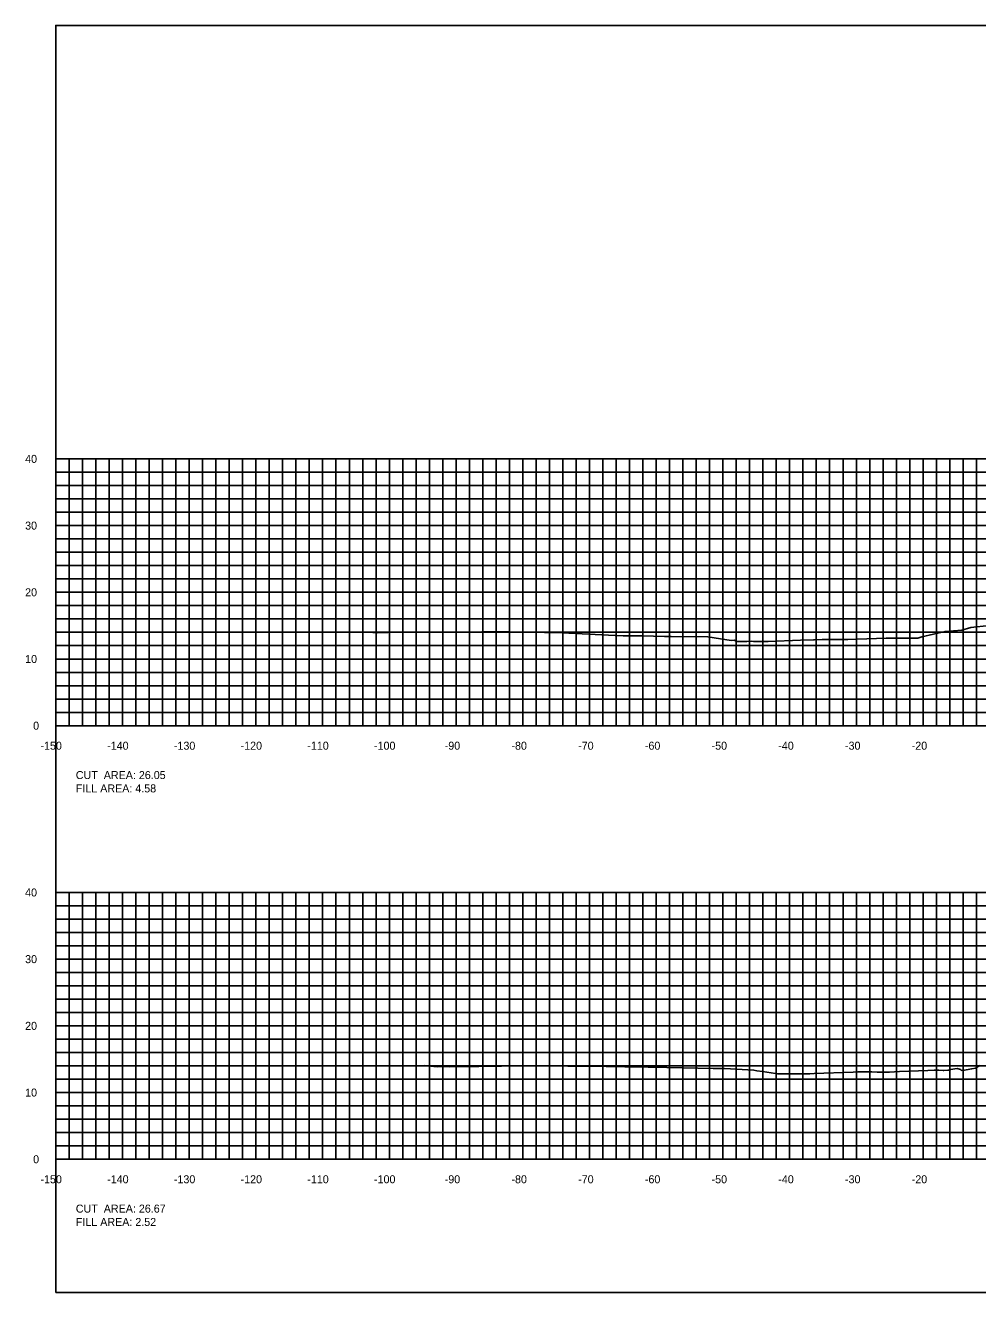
# Model space of a CAD drawing. Extents: x 1797652 to 1804159, y 242516 to 246906.
# Drawn here: x 1802149.9 to 1802292.7, y 242516 to 242706 of the extents above; entities that cross this region are included whole.
import ezdxf

# ---------------------------------------------------------------- set-up
doc = ezdxf.new("R2010")
doc.units = 0
for name, color, linetype in [('10', 7, 'Continuous'), ('31', 7, 'Continuous'), ('60', 7, 'Continuous'), ('Level 62', 7, 'Continuous'), ('M-ROADS', 7, 'Continuous')]:
    doc.layers.add(name, color=color, linetype=linetype)

msp = doc.modelspace()

# ---------------------------------------------------------------- linework, layer by layer
msp.add_lwpolyline([(1802154.49, 242516), (1802454.49, 242516), (1802454.49, 242706), (1802154.49, 242706)], close=True)
at = {"layer": '60'}
for p, q in [((1802154.43, 242641), (1802154.49, 242641)), ((1802154.49, 242601), (1802154.49, 242641)), ((1802154.43, 242631), (1802154.49, 242631)), ((1802154.43, 242621), (1802154.49, 242621)), ((1802154.43, 242611), (1802154.49, 242611)), ((1802154.43, 242601), (1802154.49, 242601)), ((1802154.49, 242601), (1802454.49, 242601)), ((1802154.49, 242600.94), (1802154.49, 242601)), ((1802164.49, 242600.94), (1802164.49, 242601)), ((1802174.49, 242600.94), (1802174.49, 242601)), ((1802184.49, 242600.94), (1802184.49, 242601)), ((1802194.49, 242600.94), (1802194.49, 242601)), ((1802204.49, 242600.94), (1802204.49, 242601)), ((1802214.49, 242600.94), (1802214.49, 242601)), ((1802224.49, 242600.94), (1802224.49, 242601)), ((1802234.49, 242600.94), (1802234.49, 242601)), ((1802244.49, 242600.94), (1802244.49, 242601)), ((1802254.49, 242600.94), (1802254.49, 242601)), ((1802264.49, 242600.94), (1802264.49, 242601)), ((1802274.49, 242600.94), (1802274.49, 242601)), ((1802284.49, 242600.94), (1802284.49, 242601)), ((1802154.43, 242576), (1802154.49, 242576)), ((1802154.49, 242536), (1802154.49, 242576)), ((1802154.43, 242566), (1802154.49, 242566)), ((1802154.43, 242556), (1802154.49, 242556)), ((1802154.43, 242546), (1802154.49, 242546)), ((1802154.43, 242536), (1802154.49, 242536)), ((1802154.49, 242536), (1802454.49, 242536)), ((1802154.49, 242535.94), (1802154.49, 242536)), ((1802164.49, 242535.94), (1802164.49, 242536)), ((1802174.49, 242535.94), (1802174.49, 242536)), ((1802184.49, 242535.94), (1802184.49, 242536)), ((1802194.49, 242535.94), (1802194.49, 242536)), ((1802204.49, 242535.94), (1802204.49, 242536)), ((1802214.49, 242535.94), (1802214.49, 242536)), ((1802224.49, 242535.94), (1802224.49, 242536)), ((1802234.49, 242535.94), (1802234.49, 242536)), ((1802244.49, 242535.94), (1802244.49, 242536)), ((1802254.49, 242535.94), (1802254.49, 242536)), ((1802264.49, 242535.94), (1802264.49, 242536)), ((1802274.49, 242535.94), (1802274.49, 242536)), ((1802284.49, 242535.94), (1802284.49, 242536))]:
    msp.add_line(p, q, dxfattribs=at)
at = {"layer": 'Level 62'}
for p, q in [((1802154.49, 242641), (1802454.49, 242641)), ((1802154.49, 242601), (1802154.49, 242641)), ((1802156.49, 242601), (1802156.49, 242641)), ((1802158.49, 242601), (1802158.49, 242641)), ((1802160.49, 242601), (1802160.49, 242641)), ((1802162.49, 242601), (1802162.49, 242641)), ((1802164.49, 242601), (1802164.49, 242641)), ((1802166.49, 242601), (1802166.49, 242641)), ((1802168.49, 242601), (1802168.49, 242641)), ((1802170.49, 242601), (1802170.49, 242641)), ((1802172.49, 242601), (1802172.49, 242641)), ((1802174.49, 242601), (1802174.49, 242641)), ((1802176.49, 242601), (1802176.49, 242641)), ((1802178.49, 242601), (1802178.49, 242641)), ((1802180.49, 242601), (1802180.49, 242641)), ((1802182.49, 242601), (1802182.49, 242641)), ((1802184.49, 242601), (1802184.49, 242641)), ((1802186.49, 242601), (1802186.49, 242641)), ((1802188.49, 242601), (1802188.49, 242641)), ((1802190.49, 242601), (1802190.49, 242641)), ((1802192.49, 242601), (1802192.49, 242641)), ((1802194.49, 242601), (1802194.49, 242641)), ((1802196.49, 242601), (1802196.49, 242641)), ((1802198.49, 242601), (1802198.49, 242641)), ((1802200.49, 242601), (1802200.49, 242641)), ((1802202.49, 242601), (1802202.49, 242641)), ((1802204.49, 242601), (1802204.49, 242641)), ((1802206.49, 242601), (1802206.49, 242641)), ((1802208.49, 242601), (1802208.49, 242641)), ((1802210.49, 242601), (1802210.49, 242641)), ((1802212.49, 242601), (1802212.49, 242641)), ((1802214.49, 242601), (1802214.49, 242641)), ((1802216.49, 242601), (1802216.49, 242641)), ((1802218.49, 242601), (1802218.49, 242641)), ((1802220.49, 242601), (1802220.49, 242641)), ((1802222.49, 242601), (1802222.49, 242641)), ((1802224.49, 242601), (1802224.49, 242641)), ((1802226.49, 242601), (1802226.49, 242641)), ((1802228.49, 242601), (1802228.49, 242641)), ((1802230.49, 242601), (1802230.49, 242641)), ((1802232.49, 242601), (1802232.49, 242641)), ((1802234.49, 242601), (1802234.49, 242641)), ((1802236.49, 242601), (1802236.49, 242641)), ((1802238.49, 242601), (1802238.49, 242641)), ((1802240.49, 242601), (1802240.49, 242641)), ((1802242.49, 242601), (1802242.49, 242641)), ((1802244.49, 242601), (1802244.49, 242641)), ((1802246.49, 242601), (1802246.49, 242641)), ((1802248.49, 242601), (1802248.49, 242641)), ((1802250.49, 242601), (1802250.49, 242641)), ((1802252.49, 242601), (1802252.49, 242641)), ((1802254.49, 242601), (1802254.49, 242641)), ((1802256.49, 242601), (1802256.49, 242641)), ((1802258.49, 242601), (1802258.49, 242641)), ((1802260.49, 242601), (1802260.49, 242641)), ((1802262.49, 242601), (1802262.49, 242641)), ((1802264.49, 242601), (1802264.49, 242641)), ((1802266.49, 242601), (1802266.49, 242641)), ((1802268.49, 242601), (1802268.49, 242641)), ((1802270.49, 242601), (1802270.49, 242641)), ((1802272.49, 242601), (1802272.49, 242641)), ((1802274.49, 242601), (1802274.49, 242641)), ((1802276.49, 242601), (1802276.49, 242641)), ((1802278.49, 242601), (1802278.49, 242641)), ((1802280.49, 242601), (1802280.49, 242641)), ((1802282.49, 242601), (1802282.49, 242641)), ((1802284.49, 242601), (1802284.49, 242641)), ((1802286.49, 242601), (1802286.49, 242641)), ((1802288.49, 242601), (1802288.49, 242641)), ((1802290.49, 242601), (1802290.49, 242641)), ((1802292.49, 242601), (1802292.49, 242641)), ((1802154.49, 242639), (1802454.49, 242639)), ((1802154.49, 242637), (1802454.49, 242637)), ((1802154.49, 242635), (1802454.49, 242635)), ((1802154.49, 242633), (1802454.49, 242633)), ((1802154.49, 242631), (1802454.49, 242631)), ((1802154.49, 242629), (1802454.49, 242629)), ((1802154.49, 242627), (1802454.49, 242627)), ((1802154.49, 242625), (1802454.49, 242625)), ((1802154.49, 242623), (1802454.49, 242623)), ((1802154.49, 242621), (1802454.49, 242621)), ((1802154.49, 242619), (1802454.49, 242619)), ((1802154.49, 242617), (1802454.49, 242617)), ((1802154.49, 242615), (1802454.49, 242615)), ((1802154.49, 242613), (1802454.49, 242613)), ((1802154.49, 242611), (1802454.49, 242611)), ((1802154.49, 242609), (1802454.49, 242609)), ((1802154.49, 242607), (1802454.49, 242607)), ((1802154.49, 242605), (1802454.49, 242605)), ((1802154.49, 242603), (1802454.49, 242603)), ((1802154.49, 242601), (1802454.49, 242601)), ((1802154.49, 242576), (1802454.49, 242576)), ((1802154.49, 242536), (1802154.49, 242576)), ((1802156.49, 242536), (1802156.49, 242576)), ((1802158.49, 242536), (1802158.49, 242576)), ((1802160.49, 242536), (1802160.49, 242576)), ((1802162.49, 242536), (1802162.49, 242576)), ((1802164.49, 242536), (1802164.49, 242576)), ((1802166.49, 242536), (1802166.49, 242576)), ((1802168.49, 242536), (1802168.49, 242576)), ((1802170.49, 242536), (1802170.49, 242576)), ((1802172.49, 242536), (1802172.49, 242576)), ((1802174.49, 242536), (1802174.49, 242576)), ((1802176.49, 242536), (1802176.49, 242576)), ((1802178.49, 242536), (1802178.49, 242576)), ((1802180.49, 242536), (1802180.49, 242576)), ((1802182.49, 242536), (1802182.49, 242576)), ((1802184.49, 242536), (1802184.49, 242576)), ((1802186.49, 242536), (1802186.49, 242576)), ((1802188.49, 242536), (1802188.49, 242576)), ((1802190.49, 242536), (1802190.49, 242576)), ((1802192.49, 242536), (1802192.49, 242576)), ((1802194.49, 242536), (1802194.49, 242576)), ((1802196.49, 242536), (1802196.49, 242576)), ((1802198.49, 242536), (1802198.49, 242576)), ((1802200.49, 242536), (1802200.49, 242576)), ((1802202.49, 242536), (1802202.49, 242576)), ((1802204.49, 242536), (1802204.49, 242576)), ((1802206.49, 242536), (1802206.49, 242576)), ((1802208.49, 242536), (1802208.49, 242576)), ((1802210.49, 242536), (1802210.49, 242576)), ((1802212.49, 242536), (1802212.49, 242576)), ((1802214.49, 242536), (1802214.49, 242576)), ((1802216.49, 242536), (1802216.49, 242576)), ((1802218.49, 242536), (1802218.49, 242576)), ((1802220.49, 242536), (1802220.49, 242576)), ((1802222.49, 242536), (1802222.49, 242576)), ((1802224.49, 242536), (1802224.49, 242576)), ((1802226.49, 242536), (1802226.49, 242576)), ((1802228.49, 242536), (1802228.49, 242576)), ((1802230.49, 242536), (1802230.49, 242576)), ((1802232.49, 242536), (1802232.49, 242576)), ((1802234.49, 242536), (1802234.49, 242576)), ((1802236.49, 242536), (1802236.49, 242576)), ((1802238.49, 242536), (1802238.49, 242576)), ((1802240.49, 242536), (1802240.49, 242576)), ((1802242.49, 242536), (1802242.49, 242576)), ((1802244.49, 242536), (1802244.49, 242576)), ((1802246.49, 242536), (1802246.49, 242576)), ((1802248.49, 242536), (1802248.49, 242576)), ((1802250.49, 242536), (1802250.49, 242576)), ((1802252.49, 242536), (1802252.49, 242576)), ((1802254.49, 242536), (1802254.49, 242576)), ((1802256.49, 242536), (1802256.49, 242576)), ((1802258.49, 242536), (1802258.49, 242576)), ((1802260.49, 242536), (1802260.49, 242576)), ((1802262.49, 242536), (1802262.49, 242576)), ((1802264.49, 242536), (1802264.49, 242576)), ((1802266.49, 242536), (1802266.49, 242576)), ((1802268.49, 242536), (1802268.49, 242576)), ((1802270.49, 242536), (1802270.49, 242576)), ((1802272.49, 242536), (1802272.49, 242576)), ((1802274.49, 242536), (1802274.49, 242576)), ((1802276.49, 242536), (1802276.49, 242576)), ((1802278.49, 242536), (1802278.49, 242576)), ((1802280.49, 242536), (1802280.49, 242576)), ((1802282.49, 242536), (1802282.49, 242576)), ((1802284.49, 242536), (1802284.49, 242576)), ((1802286.49, 242536), (1802286.49, 242576)), ((1802288.49, 242536), (1802288.49, 242576)), ((1802290.49, 242536), (1802290.49, 242576)), ((1802292.49, 242536), (1802292.49, 242576)), ((1802154.49, 242574), (1802454.49, 242574)), ((1802154.49, 242572), (1802454.49, 242572)), ((1802154.49, 242570), (1802454.49, 242570)), ((1802154.49, 242568), (1802454.49, 242568)), ((1802154.49, 242566), (1802454.49, 242566)), ((1802154.49, 242564), (1802454.49, 242564)), ((1802154.49, 242562), (1802454.49, 242562)), ((1802154.49, 242560), (1802454.49, 242560)), ((1802154.49, 242558), (1802454.49, 242558)), ((1802154.49, 242556), (1802454.49, 242556)), ((1802154.49, 242554), (1802454.49, 242554)), ((1802154.49, 242552), (1802454.49, 242552)), ((1802154.49, 242550), (1802454.49, 242550)), ((1802154.49, 242548), (1802454.49, 242548)), ((1802154.49, 242546), (1802454.49, 242546)), ((1802154.49, 242544), (1802454.49, 242544)), ((1802154.49, 242542), (1802454.49, 242542)), ((1802154.49, 242540), (1802454.49, 242540)), ((1802154.49, 242538), (1802454.49, 242538)), ((1802154.49, 242536), (1802454.49, 242536))]:
    msp.add_line(p, q, dxfattribs=at)
at = {"layer": 'M-ROADS'}
for points in [[(1802202.03, 242614.98), (1802202.64, 242614.93), (1802204.32, 242614.97), (1802207.14, 242615), (1802207.81, 242615), (1802212.75, 242615.04), (1802213.55, 242615.04), (1802215.54, 242615.04), (1802218.36, 242615.05), (1802221.28, 242615.05), (1802222.45, 242615.05), (1802230.38, 242614.94), (1802238.36, 242614.51), (1802239.54, 242614.49), (1802242.43, 242614.46), (1802245.73, 242614.37), (1802246.75, 242614.38), (1802252.21, 242614.32), (1802255.71, 242613.76), (1802256.23, 242613.8), (1802256.48, 242613.63), (1802257.59, 242613.64), (1802258.09, 242613.63), (1802258.83, 242613.65), (1802259.09, 242613.64), (1802259.65, 242613.61), (1802259.94, 242613.62), (1802261.26, 242613.64), (1802266.12, 242613.81), (1802268.09, 242613.87), (1802268.24, 242613.89), (1802269.38, 242613.92), (1802270.02, 242613.92), (1802270.13, 242613.92), (1802270.3, 242613.91), (1802271.08, 242613.91), (1802271.58, 242613.9), (1802272.65, 242613.92), (1802273.19, 242613.92), (1802276.08, 242614.02), (1802278.95, 242614.11), (1802279.49, 242614.12), (1802280.55, 242614.14), (1802281.06, 242614.12), (1802281.84, 242614.13), (1802282.01, 242614.12), (1802282.11, 242614.12), (1802282.74, 242614.12), (1802283.73, 242614.13), (1802284.33, 242614.33), (1802287.78, 242615.13), (1802290.3, 242615.33), (1802291.67, 242615.72), (1802294.4, 242616.03)], [(1802209.72, 242550.05), (1802211.66, 242549.88), (1802212.06, 242549.89), (1802213.49, 242549.88), (1802214.15, 242549.9), (1802214.61, 242549.9), (1802217.9, 242549.92), (1802224.71, 242550.01), (1802224.77, 242550.01), (1802224.85, 242550.01), (1802227.54, 242550.01), (1802228.55, 242550.01), (1802229.96, 242549.99), (1802231.22, 242549.97), (1802231.46, 242549.97), (1802232.46, 242549.96), (1802234.14, 242549.94), (1802239.77, 242549.88), (1802243.29, 242549.79), (1802244.18, 242549.79), (1802246.08, 242549.78), (1802253.01, 242549.63), (1802254.71, 242549.62), (1802259.12, 242549.35), (1802259.59, 242549.28), (1802260.43, 242549.17), (1802262.37, 242548.86), (1802262.71, 242548.79), (1802262.76, 242548.8), (1802263.29, 242548.81), (1802264.37, 242548.83), (1802264.57, 242548.82), (1802264.87, 242548.83), (1802265.49, 242548.83), (1802265.93, 242548.82), (1802267.19, 242548.82), (1802267.54, 242548.83), (1802268.17, 242548.86), (1802274.03, 242549.08), (1802274.69, 242549.09), (1802275.28, 242549.09), (1802276.31, 242549.09), (1802276.83, 242549.09), (1802277.59, 242549.08), (1802277.75, 242549.07), (1802277.86, 242549.07), (1802278.46, 242549.07), (1802279.48, 242549.08), (1802280.98, 242549.15), (1802285.23, 242549.33), (1802286.15, 242549.34), (1802286.84, 242549.34), (1802287.5, 242549.33), (1802287.58, 242549.32), (1802288.19, 242549.34), (1802288.39, 242549.34), (1802288.58, 242549.47), (1802289.6, 242549.61), (1802290.12, 242549.44), (1802290.24, 242549.33), (1802290.33, 242549.37), (1802290.42, 242549.33), (1802291.79, 242549.58), (1802292.34, 242549.64), (1802292.99, 242550.05)]]:
    msp.add_lwpolyline(points, dxfattribs=at)

# ---------------------------------------------------------------- texts
at = {"layer": '10'}
for s, p in [('-150', (1802152.19, 242597.4)), ('-140', (1802162.19, 242597.4)), ('-130', (1802172.19, 242597.4)), ('-120', (1802182.19, 242597.4)), ('-110', (1802192.19, 242597.4)), ('-100', (1802202.19, 242597.4)), ('-90', (1802212.79, 242597.4)), ('-80', (1802222.79, 242597.4)), ('-70', (1802232.79, 242597.4)), ('-60', (1802242.79, 242597.4)), ('-50', (1802252.79, 242597.4)), ('-40', (1802262.79, 242597.4)), ('-30', (1802272.79, 242597.4)), ('-20', (1802282.79, 242597.4)), ('CUT  AREA: 26.05', (1802157.49, 242593)), ('FILL AREA: 4.58', (1802157.49, 242591)), ('-150', (1802152.19, 242532.4)), ('-140', (1802162.19, 242532.4)), ('-130', (1802172.19, 242532.4)), ('-120', (1802182.19, 242532.4)), ('-110', (1802192.19, 242532.4)), ('-100', (1802202.19, 242532.4)), ('-90', (1802212.79, 242532.4)), ('-80', (1802222.79, 242532.4)), ('-70', (1802232.79, 242532.4)), ('-60', (1802242.79, 242532.4)), ('-50', (1802252.79, 242532.4)), ('-40', (1802262.79, 242532.4)), ('-30', (1802272.79, 242532.4)), ('-20', (1802282.79, 242532.4)), ('CUT  AREA: 26.67', (1802157.49, 242528)), ('FILL AREA: 2.52', (1802157.49, 242526))]:
    msp.add_text(s, height=1.2, dxfattribs=at).set_placement(p)
at = {"layer": '31'}
for s, p in [('40', (1802149.89, 242640.4)), ('30', (1802149.89, 242630.4)), ('20', (1802149.89, 242620.4)), ('10', (1802149.89, 242610.4)), ('0', (1802151.09, 242600.4)), ('40', (1802149.89, 242575.4)), ('30', (1802149.89, 242565.4)), ('20', (1802149.89, 242555.4)), ('10', (1802149.89, 242545.4)), ('0', (1802151.09, 242535.4))]:
    msp.add_text(s, height=1.2, dxfattribs=at).set_placement(p)
at = {"layer": '60'}
for p in [(1802154.49, 242601), (1802154.49, 242536)]:
    msp.add_text('-', height=0.0001, dxfattribs=at).set_placement(p)

doc.saveas('drawing.dxf')
